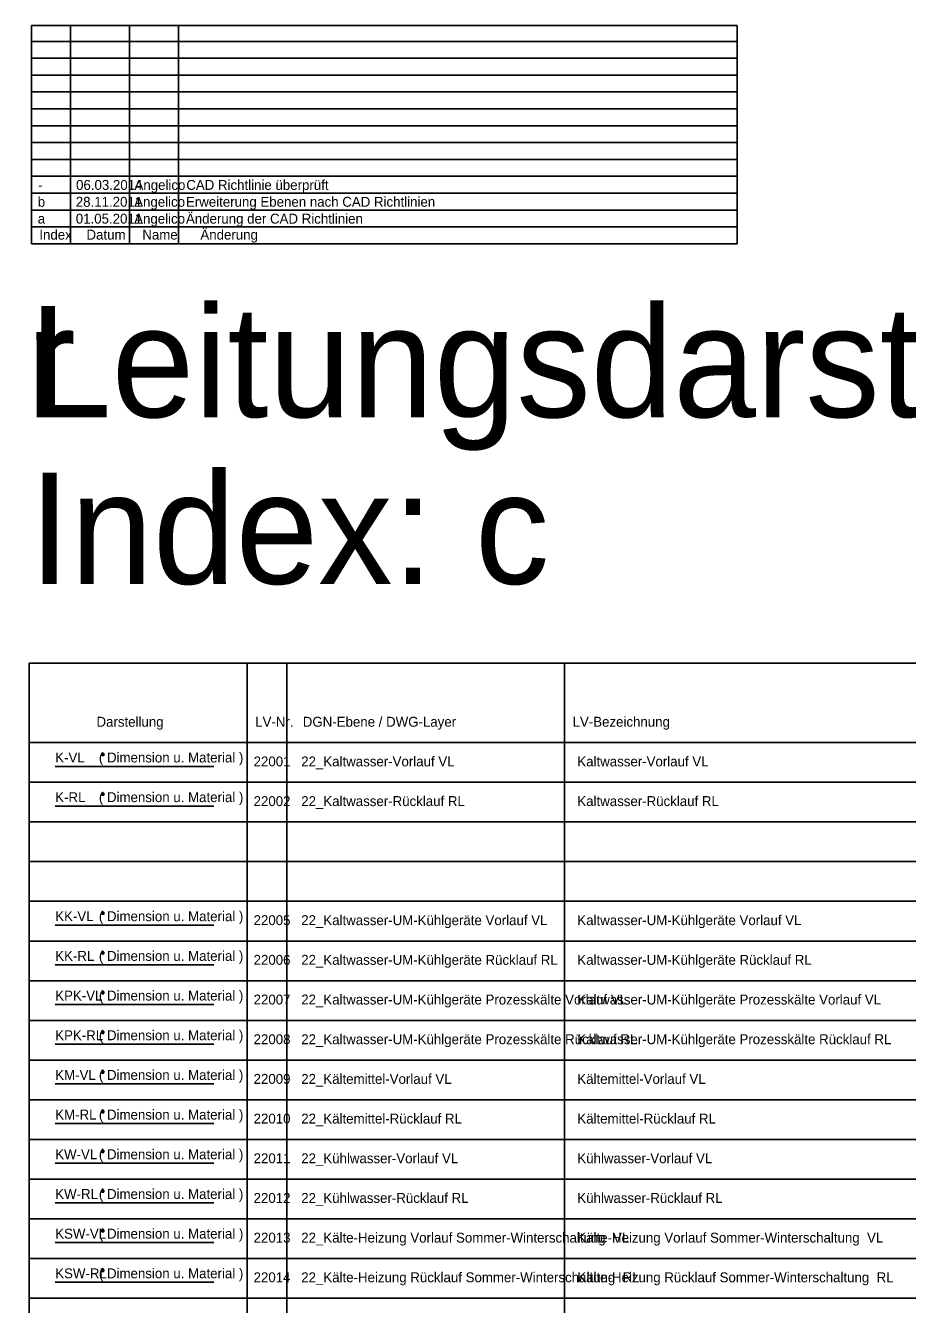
# Model space of a CAD drawing. Extents: x -29 to 48, y -113 to 16.
# Drawn here: x -0.09 to 22.14, y -16.16 to 16.07 of the extents above; entities that cross this region are included whole.
import ezdxf

# ---------------------------------------------------------------- set-up
doc = ezdxf.new("R2010")
doc.units = 0
for name, color, linetype in [('22_Kaltwasser-Rücklauf RL', 7, 'Continuous'), ('22_Kaltwasser-UM-Kühlgeräte Prozesskälte Rücklauf RL', 7, 'Continuous'), ('22_Kaltwasser-UM-Kühlgeräte Prozesskälte Vorlauf VL', 7, 'Continuous'), ('22_Kaltwasser-UM-Kühlgeräte Rücklauf RL', 7, 'Continuous'), ('22_Kaltwasser-UM-Kühlgeräte Vorlauf VL', 7, 'Continuous'), ('22_Kaltwasser-Vorlauf VL', 7, 'Continuous'), ('22_Kälte-Heizung Rücklauf Sommer-Winterschaltung  RL', 7, 'Continuous'), ('22_Kälte-Heizung Vorlauf Sommer-Winterschaltung  VL', 7, 'Continuous'), ('22_Kältemittel-Rücklauf RL', 7, 'Continuous'), ('22_Kältemittel-Vorlauf VL', 7, 'Continuous'), ('22_Kühlwasser-Rücklauf RL', 7, 'Continuous'), ('22_Kühlwasser-Vorlauf VL', 7, 'Continuous'), ('Default', 7, 'Continuous')]:
    doc.layers.add(name, color=color, linetype=linetype)

msp = doc.modelspace()

# ---------------------------------------------------------------- linework, layer by layer
at = {"layer": '22_Kaltwasser-Rücklauf RL'}
for p, q in [((1.816, -3.3), (1.904, -3.3)), ((1.829, -3.269), (1.891, -3.331)), ((1.891, -3.269), (1.829, -3.331)), ((1.86, -3.256), (1.86, -3.344)), ((0.66, -3.6), (4.66, -3.6))]:
    msp.add_line(p, q, dxfattribs=at)
at = {"layer": '22_Kaltwasser-UM-Kühlgeräte Prozesskälte Rücklauf RL'}
for p, q in [((1.816, -9.3), (1.904, -9.3)), ((1.829, -9.269), (1.891, -9.331)), ((1.891, -9.269), (1.829, -9.331)), ((1.86, -9.256), (1.86, -9.344)), ((0.66, -9.6), (4.66, -9.6))]:
    msp.add_line(p, q, dxfattribs=at)
at = {"layer": '22_Kaltwasser-UM-Kühlgeräte Prozesskälte Vorlauf VL'}
for p, q in [((1.816, -8.3), (1.904, -8.3)), ((1.829, -8.269), (1.891, -8.331)), ((1.891, -8.269), (1.829, -8.331)), ((1.86, -8.256), (1.86, -8.344)), ((0.66, -8.6), (4.66, -8.6))]:
    msp.add_line(p, q, dxfattribs=at)
at = {"layer": '22_Kaltwasser-UM-Kühlgeräte Rücklauf RL'}
for p, q in [((1.816, -7.3), (1.904, -7.3)), ((1.829, -7.269), (1.891, -7.331)), ((1.891, -7.269), (1.829, -7.331)), ((1.86, -7.256), (1.86, -7.344)), ((0.66, -7.6), (4.66, -7.6))]:
    msp.add_line(p, q, dxfattribs=at)
at = {"layer": '22_Kaltwasser-UM-Kühlgeräte Vorlauf VL'}
for p, q in [((1.816, -6.3), (1.904, -6.3)), ((1.829, -6.269), (1.891, -6.331)), ((1.891, -6.269), (1.829, -6.331)), ((1.86, -6.256), (1.86, -6.344)), ((0.66, -6.6), (4.66, -6.6))]:
    msp.add_line(p, q, dxfattribs=at)
at = {"layer": '22_Kaltwasser-Vorlauf VL'}
for p, q in [((1.86, -2.256), (1.86, -2.344)), ((1.86, -2.256), (1.86, -2.344)), ((1.816, -2.3), (1.904, -2.3)), ((1.816, -2.3), (1.904, -2.3)), ((1.829, -2.269), (1.891, -2.331)), ((1.891, -2.269), (1.829, -2.331)), ((1.829, -2.269), (1.891, -2.331)), ((1.891, -2.269), (1.829, -2.331)), ((0.66, -2.6), (4.66, -2.6))]:
    msp.add_line(p, q, dxfattribs=at)
at = {"layer": '22_Kälte-Heizung Rücklauf Sommer-Winterschaltung  RL'}
for p, q in [((1.816, -15.3), (1.904, -15.3)), ((1.829, -15.269), (1.891, -15.331)), ((1.891, -15.269), (1.829, -15.331)), ((1.86, -15.256), (1.86, -15.344)), ((0.66, -15.6), (4.66, -15.6))]:
    msp.add_line(p, q, dxfattribs=at)
at = {"layer": '22_Kälte-Heizung Vorlauf Sommer-Winterschaltung  VL'}
for p, q in [((1.816, -14.3), (1.904, -14.3)), ((1.829, -14.269), (1.891, -14.331)), ((1.891, -14.269), (1.829, -14.331)), ((1.86, -14.256), (1.86, -14.344)), ((0.66, -14.6), (4.66, -14.6))]:
    msp.add_line(p, q, dxfattribs=at)
at = {"layer": '22_Kältemittel-Rücklauf RL'}
for p, q in [((1.829, -11.269), (1.891, -11.331)), ((1.891, -11.269), (1.829, -11.331)), ((1.86, -11.256), (1.86, -11.344)), ((0.66, -11.6), (4.66, -11.6)), ((1.816, -11.3), (1.904, -11.3))]:
    msp.add_line(p, q, dxfattribs=at)
at = {"layer": '22_Kältemittel-Vorlauf VL'}
for p, q in [((1.816, -10.3), (1.904, -10.3)), ((1.829, -10.269), (1.891, -10.331)), ((1.891, -10.269), (1.829, -10.331)), ((1.86, -10.256), (1.86, -10.344)), ((0.66, -10.6), (4.66, -10.6))]:
    msp.add_line(p, q, dxfattribs=at)
at = {"layer": '22_Kühlwasser-Rücklauf RL'}
for p, q in [((1.816, -13.3), (1.904, -13.3)), ((1.829, -13.269), (1.891, -13.331)), ((1.891, -13.269), (1.829, -13.331)), ((1.86, -13.256), (1.86, -13.344)), ((0.66, -13.6), (4.66, -13.6))]:
    msp.add_line(p, q, dxfattribs=at)
at = {"layer": '22_Kühlwasser-Vorlauf VL'}
for p, q in [((1.816, -12.3), (1.904, -12.3)), ((1.829, -12.269), (1.891, -12.331)), ((1.891, -12.269), (1.829, -12.331)), ((1.86, -12.256), (1.86, -12.344)), ((0.66, -12.6), (4.66, -12.6))]:
    msp.add_line(p, q, dxfattribs=at)
at = {"layer": 'Default'}
for p, q in [((0.058, 10.57), (0.058, 16.069)), ((0.058, 16.069), (17.846, 16.069)), ((1.046, 10.57), (1.046, 16.069)), ((2.529, 10.57), (2.529, 16.069)), ((3.764, 10.57), (3.764, 16.069)), ((17.846, 10.57), (17.846, 16.069)), ((0.058, 15.67), (17.846, 15.67)), ((0.058, 15.245), (17.846, 15.245)), ((0.058, 14.82), (17.846, 14.82)), ((0.058, 14.395), (17.846, 14.395)), ((0.058, 13.97), (17.846, 13.97)), ((0.058, 13.545), (17.846, 13.545)), ((0.058, 13.12), (17.846, 13.12)), ((0.058, 12.695), (17.846, 12.695)), ((0.058, 12.27), (17.846, 12.27)), ((0.058, 11.845), (17.846, 11.845)), ((0.058, 11.42), (17.846, 11.42)), ((0.058, 10.995), (17.846, 10.995)), ((0.058, 10.57), (17.846, 10.57)), ((0.058, 10.57), (17.846, 10.57)), ((0, 0), (0, -107)), ((0, 0), (32, 0)), ((5.5, 0), (5.5, -107)), ((6.5, 0), (6.5, -107)), ((13.5, 0), (13.5, -107)), ((0, -2), (28.338, -2)), ((0, -2), (32, -2)), ((0, -3), (32, -3)), ((0, -4), (32, -4)), ((0, -5), (32, -5)), ((0, -6), (32, -6)), ((0, -7), (32, -7)), ((0, -8), (32, -8)), ((0, -9), (32, -9)), ((0, -10), (32, -10)), ((0, -11), (32, -11)), ((0, -12), (32, -12)), ((0, -13), (32, -13)), ((0, -14), (32, -14)), ((0, -15), (32, -15)), ((0, -16), (32, -16))]:
    msp.add_line(p, q, dxfattribs=at)

# ---------------------------------------------------------------- texts
at = {"layer": '22_Kaltwasser-Rücklauf RL'}
for s, p in [('K-RL', (0.66, -3.5)), ('( Dimension u. Material )', (1.76, -3.5))]:
    msp.add_text(s, height=0.25, dxfattribs=at).set_placement(p)
at = {"layer": '22_Kaltwasser-UM-Kühlgeräte Prozesskälte Rücklauf RL'}
for s, p in [('KPK-RL', (0.66, -9.5)), ('( Dimension u. Material )', (1.76, -9.5))]:
    msp.add_text(s, height=0.25, dxfattribs=at).set_placement(p)
at = {"layer": '22_Kaltwasser-UM-Kühlgeräte Prozesskälte Vorlauf VL'}
for s, p in [('KPK-VL', (0.66, -8.5)), ('( Dimension u. Material )', (1.76, -8.5))]:
    msp.add_text(s, height=0.25, dxfattribs=at).set_placement(p)
at = {"layer": '22_Kaltwasser-UM-Kühlgeräte Rücklauf RL'}
for s, p in [('KK-RL', (0.66, -7.5)), ('( Dimension u. Material )', (1.76, -7.5))]:
    msp.add_text(s, height=0.25, dxfattribs=at).set_placement(p)
at = {"layer": '22_Kaltwasser-UM-Kühlgeräte Vorlauf VL'}
for s, p in [('KK-VL', (0.66, -6.5)), ('( Dimension u. Material )', (1.76, -6.5))]:
    msp.add_text(s, height=0.25, dxfattribs=at).set_placement(p)
at = {"layer": '22_Kaltwasser-Vorlauf VL'}
for s, p in [('K-VL', (0.66, -2.5)), ('( Dimension u. Material )', (1.76, -2.5))]:
    msp.add_text(s, height=0.25, dxfattribs=at).set_placement(p)
at = {"layer": '22_Kälte-Heizung Rücklauf Sommer-Winterschaltung  RL'}
for s, p in [('KSW-RL', (0.66, -15.5)), ('( Dimension u. Material )', (1.76, -15.5))]:
    msp.add_text(s, height=0.25, dxfattribs=at).set_placement(p)
at = {"layer": '22_Kälte-Heizung Vorlauf Sommer-Winterschaltung  VL'}
for s, p in [('KSW-VL', (0.66, -14.5)), ('( Dimension u. Material )', (1.76, -14.5))]:
    msp.add_text(s, height=0.25, dxfattribs=at).set_placement(p)
at = {"layer": '22_Kältemittel-Rücklauf RL'}
for s, p in [('KM-RL', (0.66, -11.5)), ('( Dimension u. Material )', (1.76, -11.5))]:
    msp.add_text(s, height=0.25, dxfattribs=at).set_placement(p)
at = {"layer": '22_Kältemittel-Vorlauf VL'}
for s, p in [('KM-VL', (0.66, -10.5)), ('( Dimension u. Material )', (1.76, -10.5))]:
    msp.add_text(s, height=0.25, dxfattribs=at).set_placement(p)
at = {"layer": '22_Kühlwasser-Rücklauf RL'}
for s, p in [('KW-RL', (0.66, -13.5)), ('( Dimension u. Material )', (1.76, -13.5))]:
    msp.add_text(s, height=0.25, dxfattribs=at).set_placement(p)
at = {"layer": '22_Kühlwasser-Vorlauf VL'}
for s, p in [('( Dimension u. Material )', (1.76, -12.5)), ('KW-VL', (0.66, -12.5))]:
    msp.add_text(s, height=0.25, dxfattribs=at).set_placement(p)
at = {"layer": 'Default'}
for s, height, p in [('-     ', 0.25, (0.227, 11.928)), ('06.03.2014', 0.25, (1.185, 11.928)), ('Angelico', 0.25, (2.658, 11.928)), ('CAD Richtlinie überprüft                                                                        ', 0.25, (3.963, 11.928)), ('b     ', 0.25, (0.219, 11.503)), ('28.11.2011', 0.25, (1.178, 11.503)), ('Angelico', 0.25, (2.65, 11.503)), ('Erweiterung Ebenen nach CAD Richtlinien                                                         ', 0.25, (3.955, 11.503)), ('01.05.2011', 0.25, (1.178, 11.078)), ('Angelico', 0.25, (2.65, 11.078)), ('Änderung der CAD Richtlinien                                                                    ', 0.25, (3.955, 11.078)), ('a     ', 0.25, (0.219, 11.078)), ('Änderung', 0.25, (4.319, 10.675)), ('Index', 0.25, (0.259, 10.675)), ('Datum', 0.25, (1.448, 10.675)), ('Name', 0.25, (2.855, 10.675)), ('Musterlegende für ', 2.8, (-29, 6.2)), ('Leitungsdarstellung: Kälte ', 2.8, (0, 6.2)), ('Index: c', 2.8, (0, 2)), ('Darstellung', 0.25, (1.7, -1.6)), ('LV-Nr.', 0.25, (5.7, -1.6)), ('DGN-Ebene / DWG-Layer', 0.25, (6.9, -1.6)), ('LV-Bezeichnung', 0.25, (13.7, -1.6)), ('22001', 0.25, (5.66, -2.6)), ('22_Kaltwasser-Vorlauf VL', 0.25, (6.86, -2.6)), ('Kaltwasser-Vorlauf VL', 0.25, (13.82, -2.6)), ('22002', 0.25, (5.66, -3.6)), ('22_Kaltwasser-Rücklauf RL', 0.25, (6.86, -3.6)), ('Kaltwasser-Rücklauf RL', 0.25, (13.82, -3.6)), ('22005', 0.25, (5.66, -6.6)), ('22_Kaltwasser-UM-Kühlgeräte Vorlauf VL', 0.25, (6.86, -6.6)), ('Kaltwasser-UM-Kühlgeräte Vorlauf VL', 0.25, (13.82, -6.6)), ('22006', 0.25, (5.66, -7.6)), ('22_Kaltwasser-UM-Kühlgeräte Rücklauf RL', 0.25, (6.86, -7.6)), ('Kaltwasser-UM-Kühlgeräte Rücklauf RL', 0.25, (13.82, -7.6)), ('22007', 0.25, (5.66, -8.6)), ('22_Kaltwasser-UM-Kühlgeräte Prozesskälte Vorlauf VL', 0.25, (6.86, -8.6)), ('Kaltwasser-UM-Kühlgeräte Prozesskälte Vorlauf VL', 0.25, (13.82, -8.6)), ('22_Kaltwasser-UM-Kühlgeräte Prozesskälte Rücklauf RL', 0.25, (6.86, -9.6)), ('Kaltwasser-UM-Kühlgeräte Prozesskälte Rücklauf RL', 0.25, (13.82, -9.6)), ('22008', 0.25, (5.66, -9.6)), ('22009', 0.25, (5.66, -10.6)), ('22_Kältemittel-Vorlauf VL', 0.25, (6.86, -10.6)), ('Kältemittel-Vorlauf VL', 0.25, (13.82, -10.6)), ('22010', 0.25, (5.66, -11.6)), ('22_Kältemittel-Rücklauf RL', 0.25, (6.86, -11.6)), ('Kältemittel-Rücklauf RL', 0.25, (13.82, -11.6)), ('22011', 0.25, (5.66, -12.6)), ('22_Kühlwasser-Vorlauf VL', 0.25, (6.86, -12.6)), ('Kühlwasser-Vorlauf VL', 0.25, (13.82, -12.6)), ('22012', 0.25, (5.66, -13.6)), ('22_Kühlwasser-Rücklauf RL', 0.25, (6.86, -13.6)), ('Kühlwasser-Rücklauf RL', 0.25, (13.82, -13.6)), ('22013', 0.25, (5.66, -14.6)), ('22_Kälte-Heizung Vorlauf Sommer-Winterschaltung  VL', 0.25, (6.86, -14.6)), ('Kälte-Heizung Vorlauf Sommer-Winterschaltung  VL', 0.25, (13.82, -14.6)), ('22014', 0.25, (5.66, -15.6)), ('22_Kälte-Heizung Rücklauf Sommer-Winterschaltung  RL', 0.25, (6.86, -15.6)), ('Kälte-Heizung Rücklauf Sommer-Winterschaltung  RL', 0.25, (13.82, -15.6))]:
    msp.add_text(s, height=height, dxfattribs=at).set_placement(p)

doc.saveas('drawing.dxf')
